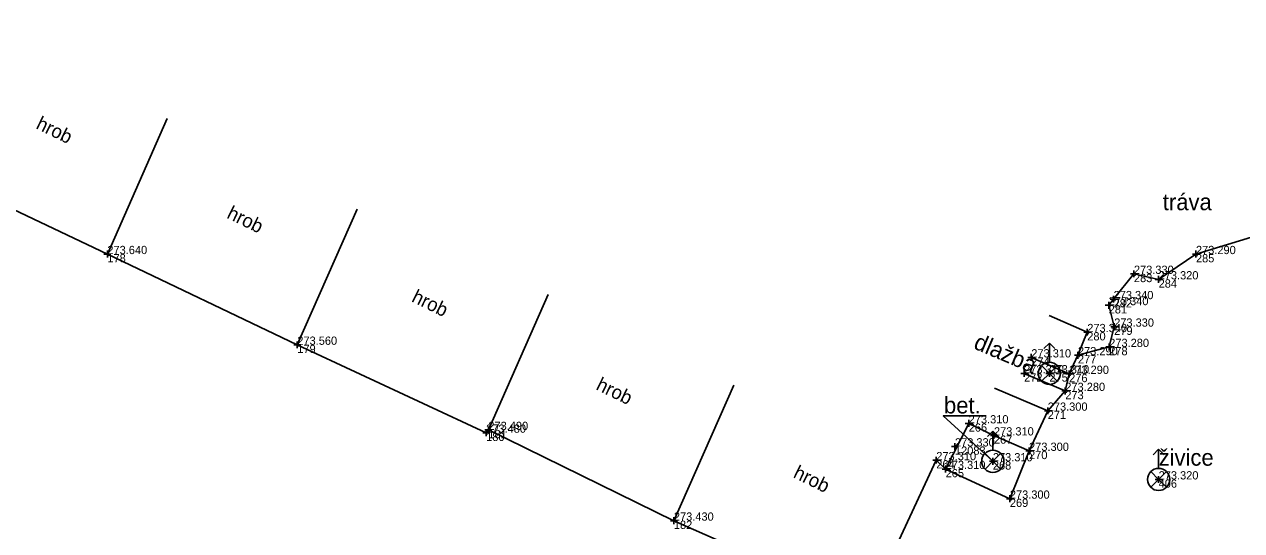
# Model space of a CAD drawing. Extents: x -776606 to -776076, y -974328 to -973875.
# Drawn here: x -776396.14 to -776373.97, y -974197.76 to -974188.55 of the extents above; entities that cross this region are included whole.
import ezdxf

# ---------------------------------------------------------------- set-up
doc = ezdxf.new("R2010")
doc.units = 0
for name, color, linetype in [('Body polohopisu', 7, 'Continuous'), ('Doplňkové značky', 7, 'Continuous'), ('Doplňující texty', 7, 'Continuous'), ('Rozhraní ploch', 7, 'Continuous'), ('Výšky bodů', 7, 'Continuous'), ('Čísla bodů', 7, 'Continuous')]:
    doc.layers.add(name, color=color, linetype=linetype)

msp = doc.modelspace()

# ---------------------------------------------------------------- linework, layer by layer
at = {"layer": 'Body polohopisu'}
for p, q in [((-776394.63, -974192.73), (-776394.693, -974192.73)), ((-776394.63, -974192.73), (-776394.63, -974192.667)), ((-776394.63, -974192.73), (-776394.568, -974192.73)), ((-776394.63, -974192.73), (-776394.63, -974192.792)), ((-776374.8, -974192.73), (-776374.863, -974192.73)), ((-776374.8, -974192.73), (-776374.8, -974192.667)), ((-776374.8, -974192.73), (-776374.738, -974192.73)), ((-776374.8, -974192.73), (-776374.8, -974192.792)), ((-776375.93, -974193.09), (-776375.993, -974193.09)), ((-776375.93, -974193.09), (-776375.93, -974193.027)), ((-776375.93, -974193.09), (-776375.868, -974193.09)), ((-776375.93, -974193.09), (-776375.93, -974193.152)), ((-776375.48, -974193.19), (-776375.542, -974193.19)), ((-776375.48, -974193.19), (-776375.48, -974193.128)), ((-776375.48, -974193.19), (-776375.417, -974193.19)), ((-776375.48, -974193.19), (-776375.48, -974193.253)), ((-776376.39, -974193.66), (-776376.39, -974193.598)), ((-776376.3, -974193.55), (-776376.363, -974193.55)), ((-776376.3, -974193.55), (-776376.3, -974193.488)), ((-776376.3, -974193.55), (-776376.238, -974193.55)), ((-776376.3, -974193.55), (-776376.3, -974193.613)), ((-776376.39, -974193.66), (-776376.453, -974193.66)), ((-776376.39, -974193.66), (-776376.328, -974193.66)), ((-776376.39, -974193.66), (-776376.39, -974193.723)), ((-776376.78, -974194.15), (-776376.78, -974194.088)), ((-776376.29, -974194.05), (-776376.353, -974194.05)), ((-776376.29, -974194.05), (-776376.29, -974193.988)), ((-776376.29, -974194.05), (-776376.228, -974194.05)), ((-776376.29, -974194.05), (-776376.29, -974194.113)), ((-776376.78, -974194.15), (-776376.843, -974194.15)), ((-776376.78, -974194.15), (-776376.718, -974194.15)), ((-776376.78, -974194.15), (-776376.78, -974194.213)), ((-776391.17, -974194.38), (-776391.233, -974194.38)), ((-776391.17, -974194.38), (-776391.17, -974194.318)), ((-776391.17, -974194.38), (-776391.108, -974194.38)), ((-776391.17, -974194.38), (-776391.17, -974194.443)), ((-776376.95, -974194.57), (-776376.95, -974194.508)), ((-776376.38, -974194.42), (-776376.443, -974194.42)), ((-776376.38, -974194.42), (-776376.38, -974194.358)), ((-776376.38, -974194.42), (-776376.318, -974194.42)), ((-776376.38, -974194.42), (-776376.38, -974194.483)), ((-776377.8, -974194.61), (-776377.863, -974194.61)), ((-776377.8, -974194.61), (-776377.8, -974194.547)), ((-776377.8, -974194.61), (-776377.738, -974194.61)), ((-776377.8, -974194.61), (-776377.8, -974194.672)), ((-776376.95, -974194.57), (-776377.013, -974194.57)), ((-776376.95, -974194.57), (-776376.888, -974194.57)), ((-776376.95, -974194.57), (-776376.95, -974194.633)), ((-776377.93, -974194.9), (-776377.993, -974194.9)), ((-776377.93, -974194.9), (-776377.93, -974194.838)), ((-776377.93, -974194.9), (-776377.868, -974194.9)), ((-776377.93, -974194.9), (-776377.93, -974194.963)), ((-776377.47, -974194.9), (-776377.532, -974194.9)), ((-776377.47, -974194.9), (-776377.47, -974194.838)), ((-776377.47, -974194.9), (-776377.407, -974194.9)), ((-776377.47, -974194.9), (-776377.47, -974194.963)), ((-776377.11, -974194.91), (-776377.172, -974194.91)), ((-776377.11, -974194.91), (-776377.11, -974194.848)), ((-776377.11, -974194.91), (-776377.047, -974194.91)), ((-776377.11, -974194.91), (-776377.11, -974194.973)), ((-776377.18, -974195.22), (-776377.18, -974195.157)), ((-776377.18, -974195.22), (-776377.243, -974195.22)), ((-776377.18, -974195.22), (-776377.118, -974195.22)), ((-776377.18, -974195.22), (-776377.18, -974195.282)), ((-776377.5, -974195.58), (-776377.562, -974195.58)), ((-776377.5, -974195.58), (-776377.5, -974195.518)), ((-776377.5, -974195.58), (-776377.438, -974195.58)), ((-776377.5, -974195.58), (-776377.5, -974195.643)), ((-776387.69, -974195.93), (-776387.69, -974195.868)), ((-776378.94, -974195.81), (-776379.003, -974195.81)), ((-776378.94, -974195.81), (-776378.94, -974195.748)), ((-776378.94, -974195.81), (-776378.878, -974195.81)), ((-776378.94, -974195.81), (-776378.94, -974195.873)), ((-776387.73, -974195.98), (-776387.792, -974195.98)), ((-776387.69, -974195.93), (-776387.753, -974195.93)), ((-776387.73, -974195.98), (-776387.73, -974195.917)), ((-776387.73, -974195.98), (-776387.667, -974195.98)), ((-776387.73, -974195.98), (-776387.73, -974196.042)), ((-776387.69, -974195.93), (-776387.628, -974195.93)), ((-776387.69, -974195.93), (-776387.69, -974195.993)), ((-776378.48, -974196.03), (-776378.542, -974196.03)), ((-776378.48, -974196.03), (-776378.48, -974195.968)), ((-776378.48, -974196.03), (-776378.417, -974196.03)), ((-776378.48, -974196.03), (-776378.48, -974196.093)), ((-776379.19, -974196.23), (-776379.253, -974196.23)), ((-776379.19, -974196.23), (-776379.19, -974196.167)), ((-776379.19, -974196.23), (-776379.128, -974196.23)), ((-776379.19, -974196.23), (-776379.19, -974196.292)), ((-776377.84, -974196.31), (-776377.902, -974196.31)), ((-776377.84, -974196.31), (-776377.84, -974196.248)), ((-776377.84, -974196.31), (-776377.777, -974196.31)), ((-776377.84, -974196.31), (-776377.84, -974196.373)), ((-776379.53, -974196.48), (-776379.593, -974196.48)), ((-776379.53, -974196.48), (-776379.53, -974196.417)), ((-776379.53, -974196.48), (-776379.468, -974196.48)), ((-776379.53, -974196.48), (-776379.53, -974196.542)), ((-776378.5, -974196.5), (-776378.562, -974196.5)), ((-776378.5, -974196.5), (-776378.5, -974196.438)), ((-776378.5, -974196.5), (-776378.438, -974196.5)), ((-776378.5, -974196.5), (-776378.5, -974196.562)), ((-776379.36, -974196.64), (-776379.422, -974196.64)), ((-776379.36, -974196.64), (-776379.36, -974196.578)), ((-776379.36, -974196.64), (-776379.297, -974196.64)), ((-776379.36, -974196.64), (-776379.36, -974196.703)), ((-776375.48, -974196.83), (-776375.542, -974196.83)), ((-776375.48, -974196.83), (-776375.48, -974196.768)), ((-776375.48, -974196.83), (-776375.417, -974196.83)), ((-776375.48, -974196.83), (-776375.48, -974196.893)), ((-776378.19, -974197.18), (-776378.253, -974197.18)), ((-776378.19, -974197.18), (-776378.19, -974197.118)), ((-776378.19, -974197.18), (-776378.128, -974197.18)), ((-776378.19, -974197.18), (-776378.19, -974197.243)), ((-776384.31, -974197.58), (-776384.373, -974197.58)), ((-776384.31, -974197.58), (-776384.31, -974197.518)), ((-776384.31, -974197.58), (-776384.248, -974197.58)), ((-776384.31, -974197.58), (-776384.31, -974197.643))]:
    msp.add_line(p, q, dxfattribs=at)
at = {"layer": 'Doplňkové značky'}
for p, q in [((-776377.47, -974194.35), (-776377.569, -974194.45)), ((-776377.47, -974194.698), (-776377.47, -974194.35)), ((-776377.47, -974194.35), (-776377.37, -974194.45)), ((-776377.47, -974194.9), (-776377.612, -974194.758)), ((-776377.47, -974194.9), (-776377.328, -974194.758)), ((-776377.47, -974194.9), (-776377.612, -974195.042)), ((-776377.47, -974194.9), (-776377.47, -974194.9)), ((-776377.47, -974194.9), (-776377.328, -974195.042)), ((-776378.5, -974195.949), (-776378.6, -974196.05)), ((-776378.5, -974196.298), (-776378.5, -974195.949)), ((-776378.5, -974195.949), (-776378.4, -974196.05)), ((-776375.48, -974196.28), (-776375.579, -974196.38)), ((-776375.48, -974196.628), (-776375.48, -974196.28)), ((-776375.48, -974196.28), (-776375.38, -974196.38)), ((-776378.5, -974196.5), (-776378.642, -974196.358)), ((-776378.5, -974196.5), (-776378.642, -974196.642)), ((-776378.5, -974196.5), (-776378.358, -974196.358)), ((-776378.5, -974196.5), (-776378.5, -974196.5)), ((-776378.5, -974196.5), (-776378.358, -974196.642)), ((-776375.48, -974196.83), (-776375.622, -974196.688)), ((-776375.48, -974196.83), (-776375.338, -974196.688)), ((-776375.48, -974196.83), (-776375.622, -974196.972)), ((-776375.48, -974196.83), (-776375.48, -974196.83)), ((-776375.48, -974196.83), (-776375.338, -974196.972))]:
    msp.add_line(p, q, dxfattribs=at)
for centre in [(-776377.47, -974194.9), (-776378.5, -974196.5), (-776375.48, -974196.83)]:
    msp.add_circle(centre, 0.202, dxfattribs=at)
at = {"layer": 'Doplňující texty'}
msp.add_lwpolyline([(-776378.5, -974196.5), (-776379.402, -974195.673), (-776378.622, -974195.673)], dxfattribs=at)
at = {"layer": 'Rozhraní ploch'}
for points in [[(-776396.87, -974188.55), (-776397.93, -974190.78), (-776398.07, -974191.1), (-776394.63, -974192.73), (-776391.17, -974194.38), (-776387.73, -974195.98), (-776387.69, -974195.93), (-776384.31, -974197.58), (-776380.77, -974199.14), (-776379.53, -974196.48)], [(-776394.63, -974192.73), (-776393.54, -974190.265)], [(-776376.95, -974194.57), (-776376.38, -974194.42), (-776376.29, -974194.05), (-776376.39, -974193.66), (-776376.3, -974193.55), (-776375.93, -974193.09), (-776375.48, -974193.19), (-776374.8, -974192.73), (-776373.79, -974192.42), (-776373.25, -974192.36), (-776372.33, -974190.53)], [(-776391.17, -974194.38), (-776390.08, -974191.915)], [(-776387.69, -974195.93), (-776386.6, -974193.465)], [(-776377.8, -974194.61), (-776377.11, -974194.91), (-776376.95, -974194.57), (-776376.78, -974194.15), (-776377.475, -974193.844)], [(-776377.93, -974194.9), (-776377.18, -974195.22), (-776377.11, -974194.91)], [(-776384.31, -974197.58), (-776383.22, -974195.115)], [(-776378.48, -974196.03), (-776377.84, -974196.31), (-776377.5, -974195.58), (-776378.469, -974195.171)], [(-776377.5, -974195.58), (-776377.18, -974195.22)], [(-776379.36, -974196.64), (-776378.94, -974195.81), (-776378.48, -974196.03)], [(-776379.36, -974196.64), (-776378.19, -974197.18), (-776377.84, -974196.31)], [(-776379.53, -974196.48), (-776379.36, -974196.64)]]:
    msp.add_lwpolyline(points, dxfattribs=at)

# ---------------------------------------------------------------- texts
at = {"layer": 'Doplňující texty'}
for s, height, rotation, p in [('hrob', 0.25, 333.9465, (-776395.948, -974190.437)), ('hrob', 0.25, 333.9465, (-776392.471, -974192.065)), ('hrob', 0.25, 333.9465, (-776389.104, -974193.586)), ('dlažba', 0.3, 336.8937, (-776378.87, -974194.44)), ('hrob', 0.25, 333.9465, (-776385.746, -974195.186)), ('hrob', 0.25, 333.9465, (-776382.153, -974196.787))]:
    msp.add_text(s, height=height, rotation=rotation, dxfattribs=at).set_placement(p)
for s, p in [('tráva', (-776375.404, -974191.931)), ('bet.', (-776379.39, -974195.629)), ('živice', (-776375.48, -974196.58))]:
    msp.add_text(s, height=0.3, dxfattribs=at).set_placement(p)
at = {"layer": 'Výšky bodů'}
for s, p in [('273.640', (-776394.63, -974192.73)), ('273.290', (-776374.8, -974192.73)), ('273.330', (-776375.93, -974193.09)), ('273.320', (-776375.48, -974193.19)), ('273.340', (-776376.3, -974193.55)), ('273.340', (-776376.39, -974193.66)), ('273.340', (-776376.78, -974194.15)), ('273.330', (-776376.29, -974194.05)), ('273.560', (-776391.17, -974194.38)), ('273.280', (-776376.38, -974194.42)), ('273.310', (-776377.8, -974194.61)), ('273.290', (-776376.95, -974194.57)), ('273.310', (-776377.93, -974194.9)), ('273.310', (-776377.47, -974194.9)), ('273.290', (-776377.11, -974194.91)), ('273.280', (-776377.18, -974195.22)), ('273.300', (-776377.5, -974195.58)), ('273.480', (-776387.73, -974195.98)), ('273.490', (-776387.69, -974195.93)), ('273.310', (-776378.94, -974195.81)), ('273.330', (-776379.19, -974196.23)), ('273.310', (-776378.48, -974196.03)), ('273.300', (-776377.84, -974196.31)), ('273.310', (-776379.53, -974196.48)), ('273.310', (-776379.36, -974196.64)), ('273.310', (-776378.5, -974196.5)), ('273.320', (-776375.48, -974196.83)), ('273.300', (-776378.19, -974197.18)), ('273.430', (-776384.31, -974197.58))]:
    msp.add_text(s, height=0.15, dxfattribs=at).set_placement(p)
at = {"layer": 'Čísla bodů'}
for s, p in [('178', (-776394.63, -974192.88)), ('285', (-776374.8, -974192.88)), ('283', (-776375.93, -974193.24)), ('284', (-776375.48, -974193.34)), ('282', (-776376.3, -974193.7)), ('281', (-776376.39, -974193.81)), ('279', (-776376.29, -974194.2)), ('280', (-776376.78, -974194.3)), ('179', (-776391.17, -974194.53)), ('278', (-776376.38, -974194.57)), ('274', (-776377.8, -974194.76)), ('277', (-776376.95, -974194.72)), ('272', (-776377.93, -974195.05)), ('275', (-776377.47, -974195.05)), ('276', (-776377.11, -974195.06)), ('273', (-776377.18, -974195.37)), ('271', (-776377.5, -974195.73)), ('266', (-776378.94, -974195.96)), ('180', (-776387.73, -974196.13)), ('181', (-776387.69, -974196.08)), ('267', (-776378.48, -974196.18)), ('12083', (-776379.19, -974196.38)), ('270', (-776377.84, -974196.46)), ('264', (-776379.53, -974196.63)), ('268', (-776378.5, -974196.65)), ('265', (-776379.36, -974196.79)), ('406', (-776375.48, -974196.98)), ('269', (-776378.19, -974197.33)), ('182', (-776384.31, -974197.73))]:
    msp.add_text(s, height=0.15, dxfattribs=at).set_placement(p)

doc.saveas('drawing.dxf')
